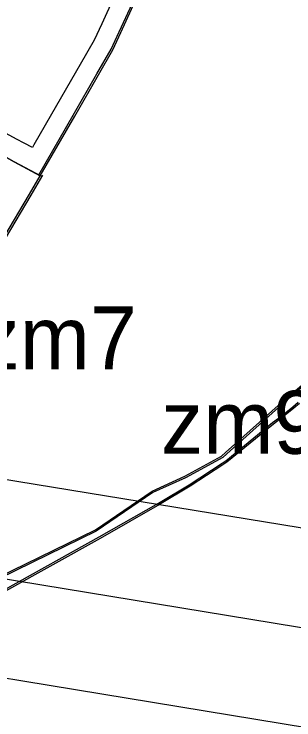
# Model space of a CAD drawing. Extents: x -555070 to -553076, y -1186731 to -1182766.
# Drawn here: x -554739.3 to -554659.4, y -1185500.5 to -1185299 of the extents above; entities that cross this region are included whole.
import ezdxf

# ---------------------------------------------------------------- set-up
doc = ezdxf.new("R2010")
doc.units = 0
for name, color, linetype in [('HRANICE_ZMENY_DO_KOO', 7, 'Continuous'), ('Level 10', 7, 'Continuous'), ('Level 13', 7, 'Continuous'), ('Level 29', 7, 'Continuous'), ('Level 56', 7, 'Continuous'), ('navrh_BV', 7, 'Continuous'), ('OBRYS_PLOCH', 7, 'Continuous'), ('rezerva_BV', 7, 'Continuous'), ('stav_DS', 7, 'Continuous')]:
    doc.layers.add(name, color=color, linetype=linetype)

msp = doc.modelspace()

# ---------------------------------------------------------------- linework, layer by layer
at = {"layer": 'HRANICE_ZMENY_DO_KOO'}
for p, q in [((-554662.18, -1185409.19), (-554650.96, -1185399.7)), ((-554678.89, -1185424.16), (-554662.18, -1185409.19)), ((-554657.81, -1185410.19), (-554659.38, -1185411.54)), ((-554659.38, -1185411.54), (-554661.4, -1185413.13)), ((-554663.5, -1185414.72), (-554665.21, -1185416.03)), ((-554661.4, -1185413.13), (-554663.5, -1185414.72)), ((-554665.21, -1185416.03), (-554678.56, -1185426.95)), ((-554680.01, -1185425.16), (-554678.89, -1185424.16)), ((-554690.53, -1185430.95), (-554680.01, -1185425.16)), ((-554678.56, -1185426.95), (-554679.64, -1185427.65)), ((-554679.64, -1185427.65), (-554689.02, -1185433.77)), ((-554699.88, -1185435.15), (-554690.53, -1185430.95)), ((-554716.05, -1185446.22), (-554699.88, -1185435.15)), ((-554689.02, -1185433.77), (-554697.8, -1185439.03)), ((-554697.8, -1185439.03), (-554714.71, -1185448.68)), ((-554743.79, -1185459.71), (-554716.05, -1185446.22)), ((-554714.71, -1185448.68), (-554741.69, -1185463.69))]:
    msp.add_line(p, q, dxfattribs=at)
for points in [[(-554732.22, -1185344.93), (-554722.41, -1185327.9), (-554715.62, -1185316.12), (-554711.52, -1185309), (-554709.27, -1185304.1), (-554703.67, -1185291.93), (-554695.45, -1185274.02), (-554692.41, -1185267.29), (-554688.86, -1185259.43), (-554682.86, -1185249.71), (-554661.74, -1185215.55), (-554660.47, -1185213.5), (-554651.98, -1185198.08), (-554642.32, -1185180.53), (-554631.22, -1185160.38)], [(-554731.33, -1185345.43), (-554739.23, -1185341.16), (-554741.42, -1185340.01), (-554746.53, -1185337.24), (-554756.64, -1185331.95), (-554765.45, -1185327.15), (-554774.75, -1185322.07)], [(-554760.02, -1185394.04), (-554752.38, -1185381.08), (-554746.62, -1185371.31), (-554744.12, -1185367.07), (-554741.75, -1185363.06), (-554734.45, -1185350.67), (-554731.1, -1185344.99)]]:
    msp.add_lwpolyline(points, dxfattribs=at)
at = {"layer": 'Level 13'}
for p, q in [((-554708.82, -1185304.31), (-554703.22, -1185292.14)), ((-554711.08, -1185309.23), (-554708.82, -1185304.31)), ((-554715.19, -1185316.37), (-554711.08, -1185309.23)), ((-554721.98, -1185328.15), (-554715.19, -1185316.37)), ((-554728.42, -1185339.33), (-554721.98, -1185328.15)), ((-554739.23, -1185341.16), (-554741.42, -1185340.01)), ((-554741.42, -1185340.01), (-554739.23, -1185341.16)), ((-554731.79, -1185345.18), (-554728.42, -1185339.33)), ((-554731.79, -1185345.18), (-554739.23, -1185341.16)), ((-554739.23, -1185341.16), (-554731.79, -1185345.18)), ((-554734.88, -1185350.42), (-554731.79, -1185345.18)), ((-554742.18, -1185362.81), (-554734.88, -1185350.42))]:
    msp.add_line(p, q, dxfattribs=at)
at = {"layer": 'Level 29'}
for points in [[(-554293.2, -1185505.39), (-554587.17, -1185457.18), (-554869.52, -1185410.99), (-555057.83, -1185309.87), (-555060.53, -1185308.42)], [(-555065.37, -1185337.55), (-554878.61, -1185437.76), (-554591.7, -1185484.82), (-554218.96, -1185545.93), (-553901.49, -1185597.94), (-553620.76, -1185643.99), (-553313.81, -1185694.25), (-553085.95, -1185731.63)], [(-555070.22, -1185366.68), (-555067.64, -1185368.06), (-554890.63, -1185462.96), (-554888.02, -1185464.13), (-554884.43, -1185465.07), (-554596.24, -1185512.45), (-554277.11, -1185564.77)]]:
    msp.add_lwpolyline(points, dxfattribs=at)
at = {"layer": 'Level 56'}
for p, q in [((-554731.79, -1185345.18), (-554739.23, -1185341.16)), ((-554734.88, -1185350.42), (-554731.79, -1185345.18)), ((-554742.18, -1185362.81), (-554734.88, -1185350.42))]:
    msp.add_line(p, q, dxfattribs=at)
msp.add_lwpolyline([(-554739.23, -1185341.16), (-554741.42, -1185340.01), (-554746.53, -1185337.24)], dxfattribs=at)
at = {"layer": 'navrh_BV'}
for p, q in [((-554739.23, -1185341.16), (-554741.42, -1185340.01)), ((-554739.23, -1185341.16), (-554741.42, -1185340.01)), ((-554731.79, -1185345.18), (-554739.23, -1185341.16)), ((-554731.79, -1185345.18), (-554739.23, -1185341.16)), ((-554734.88, -1185350.42), (-554731.79, -1185345.18)), ((-554734.88, -1185350.42), (-554731.79, -1185345.18)), ((-554742.18, -1185362.81), (-554734.88, -1185350.42)), ((-554742.18, -1185362.81), (-554734.88, -1185350.42))]:
    msp.add_line(p, q, dxfattribs=at)
at = {"layer": 'OBRYS_PLOCH'}
for p, q in [((-554739.23, -1185341.16), (-554741.42, -1185340.01)), ((-554731.79, -1185345.18), (-554739.23, -1185341.16)), ((-554734.88, -1185350.42), (-554731.79, -1185345.18)), ((-554742.18, -1185362.81), (-554734.88, -1185350.42)), ((-554665.52, -1185415.64), (-554663.8, -1185414.32)), ((-554689.29, -1185433.35), (-554679.91, -1185427.23)), ((-554690.31, -1185431.4), (-554699.63, -1185435.59)), ((-554698.05, -1185438.6), (-554689.29, -1185433.35)), ((-554699.63, -1185435.59), (-554715.8, -1185446.65)), ((-554715.8, -1185446.65), (-554743.55, -1185460.15))]:
    msp.add_line(p, q, dxfattribs=at)
for points in [[(-554620.16, -1185374.01), (-554650.64, -1185400.08), (-554661.85, -1185409.57)], [(-554661.85, -1185409.57), (-554678.56, -1185424.53), (-554679.72, -1185425.57), (-554690.31, -1185431.4)], [(-554663.8, -1185414.32), (-554661.71, -1185412.73), (-554659.7, -1185411.15), (-554658.14, -1185409.81)], [(-554679.91, -1185427.23), (-554678.86, -1185426.55), (-554665.52, -1185415.64)], [(-554773.94, -1185481.01), (-554750.17, -1185467.82), (-554741.93, -1185463.25), (-554714.96, -1185448.24), (-554698.05, -1185438.6)]]:
    msp.add_lwpolyline(points, dxfattribs=at)
at = {"layer": 'rezerva_BV'}
for p, q in [((-554708.67, -1185289.63), (-554714.27, -1185301.8)), ((-554708.82, -1185304.31), (-554703.22, -1185292.14)), ((-554708.82, -1185304.31), (-554703.22, -1185292.14)), ((-554714.27, -1185301.8), (-554716.42, -1185306.48)), ((-554711.08, -1185309.23), (-554708.82, -1185304.31)), ((-554711.08, -1185309.23), (-554708.82, -1185304.31)), ((-554716.42, -1185306.48), (-554720.39, -1185313.38)), ((-554715.19, -1185316.37), (-554711.08, -1185309.23)), ((-554715.19, -1185316.37), (-554711.08, -1185309.23)), ((-554721.98, -1185328.15), (-554715.19, -1185316.37)), ((-554721.98, -1185328.15), (-554715.19, -1185316.37)), ((-554728.42, -1185339.33), (-554721.98, -1185328.15)), ((-554728.42, -1185339.33), (-554721.98, -1185328.15)), ((-554741.42, -1185340.01), (-554739.23, -1185341.16)), ((-554741.42, -1185340.01), (-554739.23, -1185341.16)), ((-554731.79, -1185345.18), (-554728.42, -1185339.33)), ((-554731.79, -1185345.18), (-554728.42, -1185339.33)), ((-554739.23, -1185341.16), (-554731.79, -1185345.18)), ((-554739.23, -1185341.16), (-554731.79, -1185345.18))]:
    msp.add_line(p, q, dxfattribs=at)
for points in [[(-554720.39, -1185313.38), (-554727.18, -1185325.15), (-554733.62, -1185336.34), (-554734.07, -1185337.13), (-554736.41, -1185335.86)], [(-554736.41, -1185335.86), (-554738.6, -1185334.72), (-554743.71, -1185331.94)]]:
    msp.add_lwpolyline(points, dxfattribs=at)
at = {"layer": 'stav_DS'}
for p, q in [((-554665.52, -1185415.64), (-554663.8, -1185414.32)), ((-554689.29, -1185433.35), (-554679.91, -1185427.23)), ((-554690.31, -1185431.4), (-554699.63, -1185435.59)), ((-554698.05, -1185438.6), (-554689.29, -1185433.35)), ((-554699.63, -1185435.59), (-554715.8, -1185446.65)), ((-554715.8, -1185446.65), (-554743.55, -1185460.15))]:
    msp.add_line(p, q, dxfattribs=at)
for points in [[(-554620.16, -1185374.01), (-554650.64, -1185400.08), (-554661.85, -1185409.57)], [(-554661.85, -1185409.57), (-554678.56, -1185424.53), (-554679.72, -1185425.57), (-554690.31, -1185431.4)], [(-554663.8, -1185414.32), (-554661.71, -1185412.73), (-554659.7, -1185411.15), (-554658.14, -1185409.81)], [(-554679.91, -1185427.23), (-554678.86, -1185426.55), (-554665.52, -1185415.64)], [(-554773.94, -1185481.01), (-554750.17, -1185467.82), (-554741.93, -1185463.25), (-554714.96, -1185448.24), (-554698.05, -1185438.6)]]:
    msp.add_lwpolyline(points, dxfattribs=at)

# ---------------------------------------------------------------- texts
at = {"layer": 'Level 10'}
for s, p in [('zm7', (-554749.7, -1185400.44)), ('zm9d', (-554697.31, -1185424.53))]:
    msp.add_text(s, height=18, dxfattribs=at).set_placement(p)

doc.saveas('drawing.dxf')
